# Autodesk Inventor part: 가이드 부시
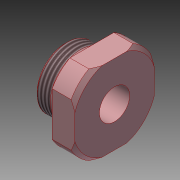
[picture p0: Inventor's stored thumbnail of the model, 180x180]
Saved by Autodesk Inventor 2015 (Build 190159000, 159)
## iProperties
Created: 2023-11
Part Number: 가이드 부시
Material: 강철, 탄소
Document SubType Name: Modeling
Designer: mdu-01
Density: 1 g/cm^3
Appearance: 기본값(1)
Author: mdu-01
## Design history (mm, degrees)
sketch "스케치1"
  geometry: L1 (-7, 0)-(6, 0); L2 (-7, 5)-(-7, 8); L3 (-7, 8)-(-3, 8); L4 (-3, 8)-(-1.614, 7.2); L5 (-1.614, 7.2)-(0, 7.2); L6 (0, 7.2)-(0, 12); L7 (0, 12)-(5, 12); L8 (6, 11)-(6, 4); L9 (6, 4)-(-6, 4); L10 (-7, 5)-(-6, 4); L11 (5, 12)-(6, 11); 3 further points
  constraints: 22 end point, 8 point on line, 5 parallel, 2 perpendicular, 1 horizontal
  dimensions: "d0" = 6 distance between parallel lines of L8 L6; "d2" = 24 diameter of L7 L1; "d3" = 7 distance between parallel lines of L2 L6; "d4" = 8 diameter of L9 L1; "d5" = 16 diameter of L3 L1; "d6" = 14.4 diameter of L5 L1; "d7" = 3 distance from line of L3.end L6; "d8" = 30 deg angle of L3 L4; "d9" = 1 distance of L2.start point (-7, 4); "d10" = 1 distance of L9.end point (-7, 4) (= d9); "d11" = 1 distance of L7.end point (6, 12) (= d9); "d12" = 1 distance of L8.start point (6, 12) (= d11)
revolve "회전1" sketch "스케치1" stored, may be unused: angle "d13" = 90 deg
feature "스레드1" dims "d14" = 10, "d15" = 0
chamfer "모따기1" distance "d16" = 0.541; stored, may be unused: second distance "d17" = 2, angle "d18" = 45 deg
sketch "스케치2"
  geometry: L1 (10.5, -10.5)-(-10.5, -10.5); L2 (-10.5, -10.5)-(-10.5, 10.5); L3 (-10.5, 10.5)-(10.5, 10.5); L4 (10.5, 10.5)-(10.5, -10.5); L5 (10.5, -10.5)-(-10.5, 10.5); L6 (-10.5, -10.5)-(10.5, 10.5); 1 further point
  constraints: 12 end point, 2 midpoint, 2 parallel, 1 horizontal, 1 perpendicular
  dimensions: "d19" = 21 distance of L2.end L3.end; "d20" = 21 distance of L1.end L2.end
extrude "돌출1" sketch "스케치2" stored distance "d21" = 0; taper "d22" = 0 deg
node "솔리드1"
